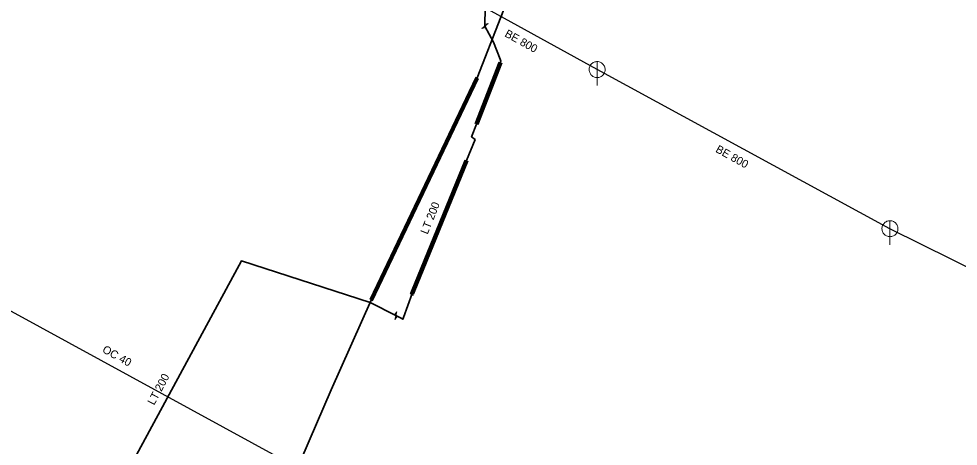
# Model space of a CAD drawing. Extents: x -659250 to -657316, y -997555 to -993684.
# Drawn here: x -658645.5 to -658528.2, y -994006.2 to -993952.8 of the extents above; entities that cross this region are included whole.
import ezdxf

# ---------------------------------------------------------------- set-up
doc = ezdxf.new("R2010")
doc.units = 0
doc.header["$LTSCALE"] = 0.4
doc.layers.add('1', color=7, linetype='Continuous')
for name, color, linetype, lineweight in [('14', 7, 'Continuous', 25), ('17', 7, 'Continuous', 25), ('22', 7, 'Continuous', 13), ('3', 7, 'Continuous', 106), ('47', 7, 'Continuous', 13)]:
    doc.layers.add(name, color=color, linetype=linetype, lineweight=lineweight)

msp = doc.modelspace()

# ---------------------------------------------------------------- linework, layer by layer
at = {"layer": '14'}
msp.add_lwpolyline([(-658473.149, -994006.14), (-658501.77, -993996.27), (-658536.69, -993978.98), (-658573.258, -993959.101), (-658589.362, -993950.17), (-658666.002, -993906.291), (-658746.41, -993860.219)], dxfattribs=at)
at = {"layer": '17', "lineweight": 35}
for points in [[(-658546.219, -993867.6), (-658553.699, -993879.42), (-658558.19, -993886.52), (-658558.1, -993886.98), (-658554.5, -993891.05), (-658538.284, -993919.318), (-658538.579, -993920.23), (-658560.34, -993935.26), (-658561.21, -993935.469), (-658572.59, -993931.21), (-658574.57, -993930.109), (-658576.14, -993930.739), (-658579.39, -993937.359), (-658588.23, -993960.149), (-658601.5, -993987.92), (-658606.489, -993999.12), (-658630.8, -994055.498)], [(-658581.741, -993928.131), (-658587.028, -993939.274), (-658587.27, -993953.67)], [(-658587.27, -993953.67), (-658586.199, -993955.67), (-658585.361, -993957.816), (-658585.27, -993958.05), (-658588.32, -993965.91), (-658588.949, -993967.5), (-658588.51, -993967.84), (-658589.59, -993970.48), (-658596.276, -993986.864), (-658596.366, -993987.092), (-658597.46, -993990.07), (-658597.51, -993990.289), (-658597.745, -993990.163), (-658598.399, -993989.84)], [(-658598.399, -993989.84), (-658601.615, -993988.207), (-658617.69, -993983), (-658634.91, -994014.859), (-658642.89, -994029.14), (-658643.64, -994039.93)]]:
    msp.add_lwpolyline(points, dxfattribs=at)
at = {"layer": '17'}
msp.add_lwpolyline([(-658533.629, -994132.381), (-658543.176, -994094.762), (-658576.06, -994083.83), (-658559.027, -994037.098), (-658707.828, -993955.756)], dxfattribs=at)
at = {"layer": '22'}
for p, q in [((-658573.258, -993961.101), (-658573.257, -993958.101)), ((-658536.69, -993980.98), (-658536.689, -993977.98))]:
    msp.add_line(p, q, dxfattribs=at)
for points in [[(-658572.258, -993959.101), (-658572.263, -993958.992), (-658572.281, -993958.884), (-658572.311, -993958.778), (-658572.351, -993958.677), (-658572.403, -993958.58), (-658572.465, -993958.49), (-658572.537, -993958.407), (-658572.617, -993958.333), (-658572.705, -993958.267), (-658572.799, -993958.212), (-658572.899, -993958.167), (-658573.004, -993958.134), (-658573.111, -993958.112), (-658573.22, -993958.102), (-658573.33, -993958.104), (-658573.438, -993958.118), (-658573.545, -993958.143), (-658573.648, -993958.18), (-658573.746, -993958.229), (-658573.838, -993958.287), (-658573.924, -993958.356), (-658574.001, -993958.433), (-658574.07, -993958.519), (-658574.129, -993958.611), (-658574.177, -993958.709), (-658574.214, -993958.812), (-658574.24, -993958.919), (-658574.254, -993959.027), (-658574.257, -993959.137), (-658574.247, -993959.246), (-658574.226, -993959.353), (-658574.192, -993959.457), (-658574.148, -993959.557), (-658574.093, -993959.652), (-658574.027, -993959.74), (-658573.953, -993959.82), (-658573.87, -993959.892), (-658573.78, -993959.954), (-658573.684, -993960.006), (-658573.582, -993960.047), (-658573.477, -993960.077), (-658573.369, -993960.095), (-658573.259, -993960.101), (-658573.15, -993960.095), (-658573.042, -993960.077), (-658572.937, -993960.048), (-658572.835, -993960.007), (-658572.738, -993959.955), (-658572.648, -993959.893), (-658572.565, -993959.822), (-658572.49, -993959.742), (-658572.425, -993959.654), (-658572.369, -993959.56), (-658572.325, -993959.46), (-658572.291, -993959.356), (-658572.269, -993959.248), (-658572.259, -993959.139)], [(-658535.69, -993978.98), (-658535.695, -993978.871), (-658535.713, -993978.763), (-658535.743, -993978.657), (-658535.783, -993978.556), (-658535.835, -993978.459), (-658535.897, -993978.369), (-658535.969, -993978.286), (-658536.049, -993978.212), (-658536.137, -993978.146), (-658536.231, -993978.091), (-658536.331, -993978.046), (-658536.436, -993978.013), (-658536.543, -993977.991), (-658536.652, -993977.981), (-658536.762, -993977.983), (-658536.87, -993977.997), (-658536.977, -993978.022), (-658537.08, -993978.059), (-658537.178, -993978.108), (-658537.27, -993978.166), (-658537.356, -993978.235), (-658537.433, -993978.312), (-658537.502, -993978.398), (-658537.561, -993978.49), (-658537.609, -993978.588), (-658537.646, -993978.691), (-658537.672, -993978.798), (-658537.686, -993978.906), (-658537.689, -993979.016), (-658537.679, -993979.125), (-658537.658, -993979.232), (-658537.624, -993979.336), (-658537.58, -993979.436), (-658537.525, -993979.531), (-658537.459, -993979.619), (-658537.385, -993979.699), (-658537.302, -993979.771), (-658537.212, -993979.833), (-658537.116, -993979.885), (-658537.014, -993979.926), (-658536.909, -993979.956), (-658536.801, -993979.974), (-658536.691, -993979.98), (-658536.582, -993979.974), (-658536.474, -993979.956), (-658536.369, -993979.927), (-658536.267, -993979.886), (-658536.17, -993979.834), (-658536.08, -993979.772), (-658535.997, -993979.701), (-658535.922, -993979.621), (-658535.857, -993979.533), (-658535.801, -993979.439), (-658535.757, -993979.339), (-658535.723, -993979.235), (-658535.701, -993979.127), (-658535.691, -993979.018)]]:
    msp.add_lwpolyline(points, close=True, dxfattribs=at)
at = {"layer": '3'}
for p, q in [((-658585.336, -993958.221), (-658588.32, -993965.91)), ((-658588.23, -993960.149), (-658601.5, -993987.92))]:
    msp.add_line(p, q, dxfattribs=at)
at = {"layer": '3', "lineweight": 100}
for p, q in [((-658585.336, -993958.221), (-658588.32, -993965.91)), ((-658588.23, -993960.149), (-658601.5, -993987.92))]:
    msp.add_line(p, q, dxfattribs=at)
at = {"layer": '3'}
msp.add_lwpolyline([(-658589.59, -993970.48), (-658596.276, -993986.864), (-658596.366, -993987.092), (-658596.426, -993987.254)], dxfattribs=at)
at = {"layer": '3', "lineweight": 100}
msp.add_lwpolyline([(-658589.59, -993970.48), (-658596.276, -993986.864), (-658596.366, -993987.092), (-658596.426, -993987.254)], dxfattribs=at)
at = {"layer": '47'}
for p, q in [((-658586.875, -993953.347), (-658587.364, -993953.492)), ((-658598.532, -993990.331), (-658598.218, -993989.928))]:
    msp.add_line(p, q, dxfattribs=at)
for points in [[(-658586.875, -993953.347), (-658587.664, -993953.992), (-658587.175, -993953.847)], [(-658598.532, -993990.331), (-658598.265, -993989.348), (-658598.579, -993989.751)]]:
    msp.add_lwpolyline(points, dxfattribs=at)

# ---------------------------------------------------------------- texts
at = {"layer": '1'}
for s, rotation, p in [('BE 800', 331, (-658584.896, -993954.916)), ('BE 800', 331, (-658558.557, -993969.351)), ('LT 200', 68, (-658594.441, -993979.755)), ('OC 40 ', 331, (-658635.148, -993994.363)), ('LT 200', 62, (-658628.592, -994001.099))]:
    msp.add_text(s, height=1, rotation=rotation, dxfattribs=at).set_placement(p)

doc.saveas('drawing.dxf')
